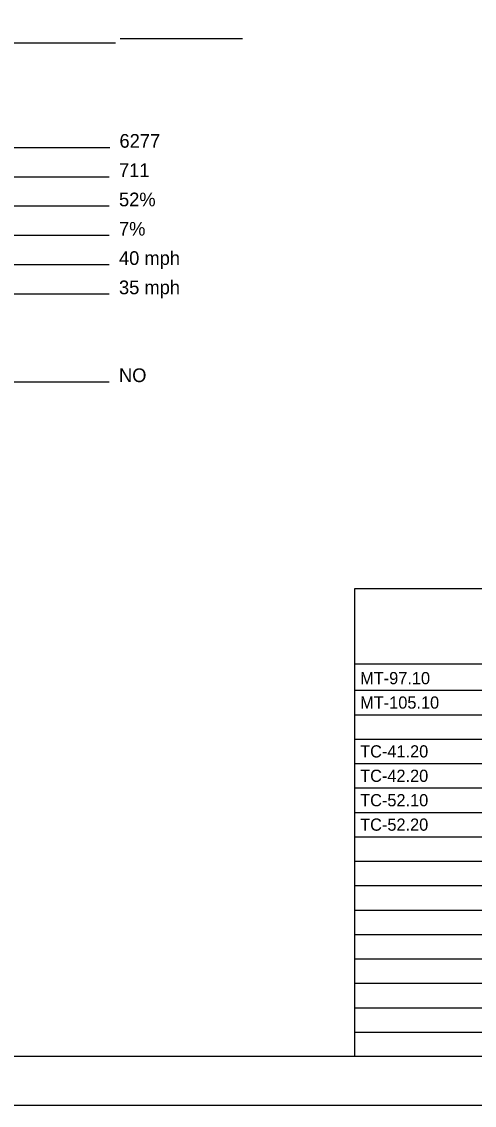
# Model space of a CAD drawing. Extents: x 0 to 34, y 0 to 22.
# Drawn here: x 6.74 to 11.37, y 0 to 11.1 of the extents above; entities that cross this region are included whole.
import ezdxf

# ---------------------------------------------------------------- set-up
doc = ezdxf.new("R2010")
doc.units = 0
for name, color, linetype in [('Default', 7, 'Continuous'), ('SH_Border', 7, 'Continuous'), ('SH_Cut_Line', 7, 'Continuous'), ('SH_Data', 7, 'Continuous'), ('SH_Text', 7, 'Continuous')]:
    doc.layers.add(name, color=color, linetype=linetype)

msp = doc.modelspace()

# ---------------------------------------------------------------- linework, layer by layer
at = {"layer": 'SH_Border'}
msp.add_lwpolyline([(1.5, 21.5), (33.5, 21.5), (33.5, 0.5), (1.5, 0.5)], close=True, dxfattribs=at)
at = {"layer": 'SH_Cut_Line'}
msp.add_lwpolyline([(0, 0), (34, 0), (34, 22), (0, 22)], close=True, dxfattribs=at)
at = {"layer": 'SH_Data'}
for p, q in [((7.7, 10.877), (3.347, 10.877)), ((9, 10.922), (7.75, 10.922)), ((7.642, 9.806), (3.871, 9.806)), ((7.637, 9.506), (4.318, 9.506)), ((7.637, 9.206), (4.604, 9.206)), ((7.637, 8.906), (4.189, 8.906)), ((7.637, 8.606), (3.346, 8.606)), ((7.637, 8.306), (3.242, 8.306)), ((7.637, 7.406), (3.267, 7.406)), ((10.15, 5.292), (23.6, 5.292)), ((10.15, 0.5), (10.15, 5.292)), ((10.15, 4.521), (23.6, 4.521)), ((10.15, 4.25), (23.6, 4.25)), ((10.15, 4), (23.6, 4)), ((10.15, 3.75), (23.6, 3.75)), ((10.15, 3.5), (23.6, 3.5)), ((10.15, 3.25), (23.6, 3.25)), ((10.15, 3), (23.6, 3)), ((10.15, 2.75), (23.6, 2.75)), ((10.15, 2.5), (23.6, 2.5)), ((10.15, 2.25), (23.6, 2.25)), ((10.15, 2), (23.6, 2)), ((10.15, 1.75), (23.6, 1.75)), ((10.15, 1.5), (23.6, 1.5)), ((10.15, 1.25), (23.6, 1.25)), ((10.15, 1), (23.6, 1)), ((10.15, 0.75), (23.6, 0.75))]:
    msp.add_line(p, q, dxfattribs=at)

# ---------------------------------------------------------------- texts
at = {"layer": 'Default'}
for s, p in [('MT-97.10', (10.205, 4.312)), ('MT-105.10', (10.205, 4.062)), ('TC-41.20', (10.205, 3.562)), ('TC-42.20', (10.205, 3.312)), ('TC-52.10', (10.205, 3.062)), ('TC-52.20', (10.205, 2.812))]:
    msp.add_text(s, height=0.125, dxfattribs=at).set_placement(p)
at = {"layer": 'SH_Text'}
for s, p in [('6277', (7.742, 9.806)), ('711', (7.737, 9.506)), ('52%', (7.737, 9.206)), ('7%', (7.737, 8.906)), ('40 mph', (7.737, 8.606)), ('35 mph', (7.737, 8.306)), ('NO', (7.737, 7.406))]:
    msp.add_text(s, height=0.14, dxfattribs=at).set_placement(p)

doc.saveas('drawing.dxf')
